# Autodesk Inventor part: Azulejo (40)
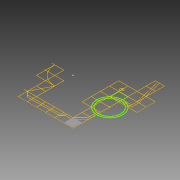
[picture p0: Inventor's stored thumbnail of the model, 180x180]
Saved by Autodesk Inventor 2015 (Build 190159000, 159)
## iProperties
Created: 2015-04
Part Number: Azulejo (40)
Material: Genérico
Document SubType Name: Modeling
Designer: Felipe
Density: 1 g/cm^3
Appearance: Padrão
Author: Felipe
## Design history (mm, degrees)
sketch "Sketch1"
  geometry: L1 (-1510, -7490)-(-1510, -6010); L2 (-3010, -1490)-(-3010, -10); L3 (-2990, 10)-(-1510, 10); L4 (-1510, -10)-(-2990, -10); L5 (-1510, -1490)-(-1510, -10); L6 (-1490, -10)-(-1490, -1490); L7 (-1490, -1490)-(-10, -1490); L8 (-10, -1510)-(-1490, -1510); L9 (-10, -2990)-(-10, -1510); L10 (-10, -5990)-(-10, -4510); L11 (-1490, -7490)-(-10, -7490); L12 (4490, -6010)-(3010, -6010); L13 (10, -1510)-(10, -2990); L14 (10, -3010)-(10, -4490); L15 (10, -4510)-(10, -5990); L16 (10, -5990)-(1490, -5990); L17 (1490, -6010)-(10, -6010); L18 (10, -7490)-(1490, -7490); L19 (1510, -5990)-(2990, -5990); L20 (2990, -6010)-(1510, -6010); L21 (1510, -7490)-(2990, -7490); L22 (4490, 1510)-(4490, 2990); L23 (4490, 10)-(4490, 1490); L24 (4490, -1490)-(4490, -10); L25 (4490, -2990)-(4490, -1510); L26 (3010, -5990)-(4490, -5990); L27 (3010, -7490)-(4490, -7490); L28 (4510, 3010)-(5990, 3010); L29 (5990, 2990)-(4510, 2990); L30 (4510, 2990)-(4510, 1510); L31 (4510, 1510)-(5990, 1510); L32 (5990, 1510)-(5990, 1740.185); L33 (5990, 1760.2)-(5990, 2259.8); L34 (5990, 2279.815)-(5990, 2990); L35 (5990, 1490)-(4510, 1490); L36 (4510, 1490)-(4510, 10); L37 (4510, 10)-(5990, 10); L38 (5990, 10)-(5990, 1490); L39 (5975.983, -10)-(4510, -10); L40 (4510, -10)-(4510, -1490); L41 (5990, -1510)-(5782.897, -1510); L42 (5782.897, -1510)-(5688.66, -1510); L43 (5668.66, -1510)-(5482.895, -1510); L44 (5482.895, -1510)-(5388.656, -1510); L45 (5368.656, -1510)-(4510, -1510); L46 (4510, -1510)-(4510, -2990); L47 (4510, -2990)-(5975.983, -2990); L48 (5990, -2975.728)-(5990, -2837.377); L49 (5990, -2837.377)-(5990, -2536.247); L50 (5990, -2500.476)-(5990, -2317.632); L51 (5990, -2317.632)-(5990, -1510); L52 (5990, -3010)-(4510, -3010); L53 (5990, -4490)-(5990, -3010); L54 (4510, -5990)-(5990, -5990); L55 (5990, -5990)-(5990, -4510); L56 (4510, -7490)-(5990, -7490); L57 (5990, -7490)-(5990, -6310); L58 (5990, -6290)-(5990, -6010); L59 (7490, 4510)-(7490, 5990); L60 (6010, 3010)-(7490, 3010); L61 (7490, 3010)-(7490, 4490); L62 (7490, 2990)-(6010, 2990); L63 (6010, 2990)-(6010, 2279.815); L64 (6010, 2259.8)-(6010, 1760.2)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; A1 r 250 centre (6000, 2010) between (5990, 2259.8) and (5990, 1760.2); A2 r 250 centre (6000, 2010) between (6010, 1760.2) and (6010, 2259.8); A3 r 270 centre (6000, 2010) between (5990, 2279.815) and (5990, 1740.185); A4 r 270 centre (6000, 2010) between (6010, 1740.185) and (6010, 2279.815); A5 r 3010.017 centre (0, 0) between (-1490, -2615.358) and (-346.554, -2990); A6 r 2990.017 centre (0, 0) between (-1490, -2592.316) and (-10, -2990); A7 r 3010.017 centre (0, 0) between (-2603.863, -1510) and (-1510, -2603.863); A8 r 2990.017 centre (0, 0) between (-2580.717, -1510) and (-1510, -2580.717); A9 r 3010.017 centre (0, 0) between (-2990, -346.554) and (-2615.358, -1490); A10 r 2990.017 centre (0, 0) between (-2990, -10) and (-2592.316, -1490); A11 r 2131.367 centre (7500, -1500) between (7490, 631.344) and (6010, 24.017); A12 r 2131.367 centre (7500, -1500) between (5975.983, -10) and (5368.656, -1490); A13 r 2131.367 centre (7500, -1500) between (5368.656, -1510) and (5975.983, -2990); A14 r 2131.367 centre (7500, -1500) between (6010, -3024.017) and (7190, -3608.703); A15 r 1831.367 centre (7500, -1500) between (7490.321, 331.342) and (6463.753, 10); A16 r 1831.367 centre (7500, -1500) between (7489.976, 331.34) and (6010, -435.196); A17 r 1831.367 centre (7500, -1500) between (5990, -463.753) and (5668.66, -1490); A18 r 1831.367 centre (7500, -1500) between (5668.66, -1510) and (5990, -2536.247); A19 r 1831.367 centre (7500, -1500) between (6010, -2564.804) and (6435.196, -2990); A20 r 1831.367 centre (7500, -1500) between (6463.753, -3010) and (7490, -3331.34); A21 r 2111.367 centre (7500, -1500) between (7490.389, 611.346) and (6024.272, 10); A22 r 2111.367 centre (7500, -1500) between (5990, -24.272) and (5388.656, -1490); A23 r 2111.367 centre (7500, -1500) between (5388.656, -1510) and (5990, -2975.728); A24 r 2111.367 centre (7500, -1500) between (6024.272, -3010) and (7210, -3591.357); A25 r 1811.367 centre (7499.986, -1499.91) between (7490.524, 311.432) and (6499.51, 10.09); A26 r 1811.367 centre (7500, -1500) between (6469.975, -10) and (6010, -469.975); A27 r 1811.367 centre (7500, -1500) between (5990, -499.524) and (5688.66, -1490); A28 r 1811.367 centre (7500, -1500) between (5688.66, -1510) and (5990, -2500.476); A29 r 1811.367 centre (7500, -1500) between (6010, -2530.025) and (6469.975, -2990); A30 r 1811.367 centre (7500, -1500) between (6499.524, -3010) and (7490, -3311.34); A31 r 449.871 centre (7499.449, -4060.672) between (7510, -4510.419) and (7521.546, -4510); A32 r 2111.367 centre (7500, -1500) between (7490.019, 611.344) and (7490.389, 611.346); A33 r 1831.367 centre (7500, -1500) between (7489.976, 331.34) and (7490.321, 331.342); A34 r 1811.367 centre (7499.986, -1499.91) between (7489.986, 311.429) and (7490.524, 311.432); A35 r 2131.367 centre (7500, -1500) between (7510, -3631.344) and (7190, -3608.703); A36 r 2131.367 centre (7500, -1500) between (7210, -3611.546) and (7490, -3631.344); 12 further points
  constraints: 718 end point, 82 point on circle, 36 centre point, 14 point on line, 3 concentric, 2 parallel, 2 perpendicular, 1 collinear, 1 horizontal, 1 vertical, 1 other
extrude "Extrusion1" new body sketch "Sketch1" distance "d0" = 60; taper "d1" = 0 deg
extrude "Extrusion2" new body sketch "Sketch1" distance "d2" = 60; taper "d3" = 0 deg
body "Solid1"
body "Solid2"
